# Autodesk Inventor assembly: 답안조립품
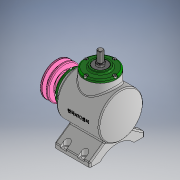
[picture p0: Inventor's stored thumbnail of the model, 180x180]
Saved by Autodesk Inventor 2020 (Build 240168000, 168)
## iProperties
Created: 2023-12
Part Number: 답안조립품
Document SubType Name: Assembly
Designer: 1강의실14
Author: 1강의실14
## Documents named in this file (17)
- C:\Users\1강의실14\Desktop\731203V1010\답안조립품.iam
- C:\Users\1강의실14\Desktop\731203V1010\본체.ipt
- C:\Users\1강의실14\Desktop\731203V1010\V-벨트풀리.ipt
- C:\Users\1강의실14\Desktop\731203V1010\메인 베벨기어.ipt
- C:\Users\1강의실14\Desktop\731203V1010\메인 축.ipt
- 메인 축.ipt
- C:\Users\1강의실14\Desktop\731203V1010\베어링 6203.ipt
- C:\Users\1강의실14\Desktop\731203V1010\볼트 M4 x 10.ipt
- C:\Users\1강의실14\Desktop\731203V1010\서브 베벨기어.ipt
- C:\Users\1강의실14\Desktop\731203V1010\서브 축.ipt
- 서브 축.ipt
- C:\Users\1강의실14\Desktop\731203V1010\오일실 17 x 32 x 8.ipt
- C:\Users\1강의실14\Desktop\731203V1010\와셔 4 x 16.ipt
- C:\Users\1강의실14\Desktop\731203V1010\육각볼트 M4 x 8.ipt
- C:\Users\1강의실14\Desktop\731203V1010\커버.ipt
- C:\Users\1강의실14\Desktop\731203V1010\키 4 x 4 x 14.ipt
- C:\Users\1강의실14\Desktop\731203V1010\키 5 x 5 x 14.ipt
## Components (1 placed, 1 different names)
1. V-벨트풀리:1
